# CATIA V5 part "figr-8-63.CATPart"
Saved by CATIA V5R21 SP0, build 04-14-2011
Part number: Part1
Bounding box of the stored display mesh (mm): x -68.924 to 54.237, y -54.052 to 120.856, z 0 to 40
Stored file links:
  D:\CATIA V5R21 E-RESOURCES\CATIA-V5R21\catia-v5r21-prt\c08-catia-v5r20-prt\c08-catia-v5r21-figr-8-63.CATPart
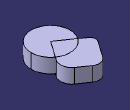
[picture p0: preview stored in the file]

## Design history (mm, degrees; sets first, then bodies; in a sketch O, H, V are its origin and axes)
Body1 (main body)
  Sketch1 on xy-plane, origin (0, 0, 0), H (1, 0, 0), V (0, 1, 0)
    circle A1 centre (0, 0) radius 54.2371
    point P1 (0, 54.2371)
    coincidence: A1 P1, P1 V
  Pad1: profile Sketch1, direction (0, 0, 1), length 40
Body2
  Sketch2 on xy-plane, origin (0, 0, 0), H (1, 0, 0), V (0, 1, 0)
    line L1 (0, 0) -> (36.9865, 52.8223)
    arc A1 centre (11.6298, 70.5772) radius 30.9549 from (36.9865, 52.8223) to (29.3848, 95.934) ccw
    line L2 (29.3848, 95.934) -> (0.2008, 116.3688)
    arc A2 centre (-14.1853, 95.8234) radius 25.0814 from (0.2008, 116.3688) to (-34.7307, 110.2094) ccw
    line L3 (-34.7307, 110.2094) -> (-66.0893, 65.4248)
    arc A3 centre (-53.2403, 56.4279) radius 15.6856 from (-66.0893, 65.4248) to (-62.2373, 43.579) ccw
    line L4 (-62.2373, 43.579) -> (0, 0)
    tangency: A1 L1, L2 A1, A2 L2, L3 A2, A3 L3, L4 A3
  Pad2: profile Sketch2, direction (0, 0, 1), length 40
